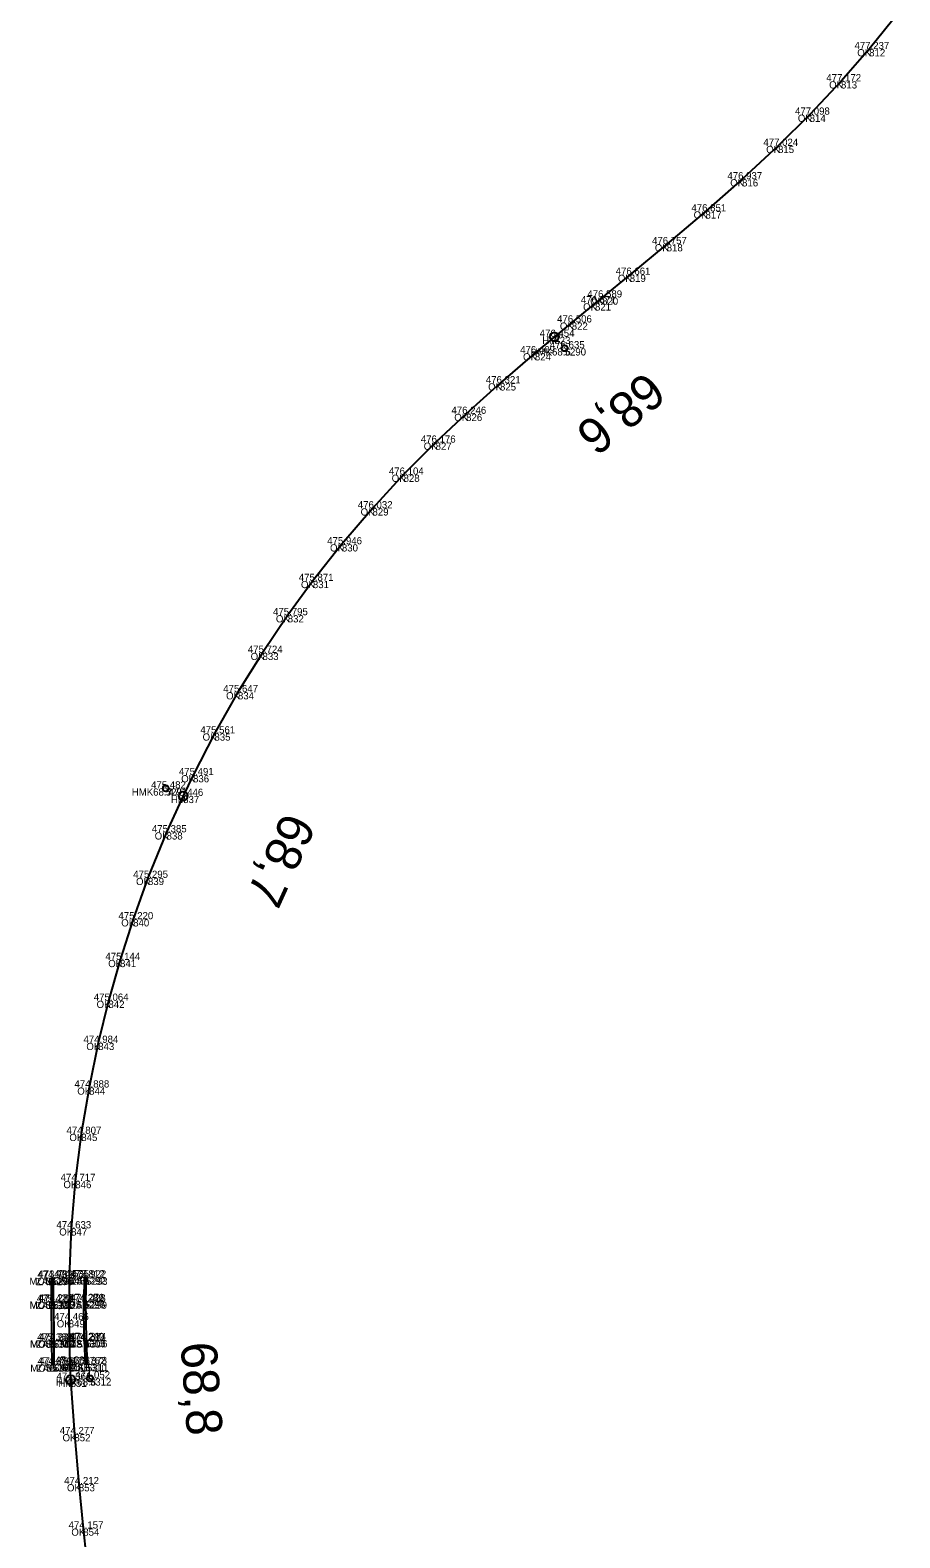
# Model space of a CAD drawing. Extents: x -621782 to -610392, y -1141853 to -1122321.
# Drawn here: x -621684.4 to -621539.3, y -1125595.1 to -1125343.5 of the extents above; entities that cross this region are included whole.
import ezdxf

# ---------------------------------------------------------------- set-up
doc = ezdxf.new("R2010")
doc.units = 0
for name, color, linetype in [('Vrstva 1', 7, 'Continuous'), ('Vrstva 17', 7, 'Continuous'), ('Vrstva 18', 7, 'Continuous'), ('Vrstva 60', 7, 'Continuous'), ('Vrstva 61', 7, 'Continuous'), ('Vrstva 62', 7, 'Continuous'), ('Vrstva 7', 7, 'Continuous')]:
    doc.layers.add(name, color=color, linetype=linetype)

msp = doc.modelspace()

# ---------------------------------------------------------------- linework, layer by layer
at = {"layer": 'Vrstva 1'}
msp.add_lwpolyline([(-621539.34, -1125340.3), (-621544.45, -1125346.63), (-621549.15, -1125352), (-621554.37, -1125357.57), (-621559.65, -1125362.78), (-621565.65, -1125368.35), (-621571.75, -1125373.71), (-621578.22, -1125379.19), (-621584.39, -1125384.29), (-621589, -1125388.09), (-621590.18, -1125389.06), (-621594.06, -1125392.26), (-621596.96, -1125394.65), (-621600.21, -1125397.39), (-621606.03, -1125402.41), (-621611.68, -1125407.5), (-621616.77, -1125412.31), (-621622.11, -1125417.66), (-621627.3, -1125423.28), (-621632.4, -1125429.28), (-621637.24, -1125435.4), (-621641.43, -1125441.12), (-621645.64, -1125447.4), (-621649.74, -1125453.97), (-621653.66, -1125460.85), (-621657.23, -1125467.81), (-621658.88, -1125471.28), (-621661.64, -1125477.36), (-621664.75, -1125484.96), (-621667.22, -1125491.87), (-621669.4, -1125498.66), (-621671.34, -1125505.47), (-621673.05, -1125512.5), (-621674.56, -1125519.95), (-621675.87, -1125527.69), (-621676.87, -1125535.56), (-621677.57, -1125543.46), (-621677.92, -1125551.62), (-621677.97, -1125558.78), (-621677.77, -1125566.05), (-621677.65, -1125568.73), (-621677.02, -1125577.81), (-621676.28, -1125586.16), (-621675.54, -1125593.57), (-621675.23, -1125596.68)], dxfattribs=at)
at = {"layer": 'Vrstva 17'}
for points in [[(-621680.71, -1125566.19), (-621680.78, -1125562.18), (-621680.84, -1125555.75), (-621680.85, -1125551.75)], [(-621675.06, -1125551.69), (-621675.15, -1125555.68), (-621675.07, -1125562.11), (-621674.92, -1125566.12)]]:
    msp.add_lwpolyline(points, dxfattribs=at)
at = {"layer": 'Vrstva 18'}
for points in [[(-621680.58, -1125551.69), (-621680.54, -1125555.65), (-621680.51, -1125555.71), (-621680.44, -1125562.17), (-621680.48, -1125562.2), (-621680.43, -1125566.19)], [(-621675.18, -1125566.13), (-621675.35, -1125562.18), (-621675.4, -1125562.1), (-621675.46, -1125555.65), (-621675.42, -1125555.59), (-621675.34, -1125551.63)]]:
    msp.add_lwpolyline(points, dxfattribs=at)
at = {"layer": 'Vrstva 60'}
for p, q in [((-621544.45, -1125346.63), (-621544.45, -1125346.63)), ((-621549.15, -1125352), (-621549.15, -1125352)), ((-621554.37, -1125357.57), (-621554.37, -1125357.57)), ((-621559.65, -1125362.78), (-621559.65, -1125362.78)), ((-621565.65, -1125368.35), (-621565.65, -1125368.35)), ((-621571.75, -1125373.71), (-621571.75, -1125373.71)), ((-621578.22, -1125379.19), (-621578.22, -1125379.19)), ((-621584.39, -1125384.29), (-621584.39, -1125384.29)), ((-621589, -1125388.09), (-621589, -1125388.09)), ((-621590.18, -1125389.06), (-621590.18, -1125389.06)), ((-621594.06, -1125392.26), (-621594.06, -1125392.26)), ((-621596.96, -1125394.65), (-621596.96, -1125394.65)), ((-621600.21, -1125397.39), (-621600.21, -1125397.39)), ((-621595.25, -1125396.57), (-621595.25, -1125396.57)), ((-621606.03, -1125402.41), (-621606.03, -1125402.41)), ((-621611.68, -1125407.5), (-621611.68, -1125407.5)), ((-621616.77, -1125412.31), (-621616.77, -1125412.31)), ((-621622.11, -1125417.66), (-621622.11, -1125417.66)), ((-621627.3, -1125423.28), (-621627.3, -1125423.28)), ((-621632.4, -1125429.28), (-621632.4, -1125429.28)), ((-621637.24, -1125435.4), (-621637.24, -1125435.4)), ((-621641.43, -1125441.12), (-621641.43, -1125441.12)), ((-621645.64, -1125447.4), (-621645.64, -1125447.4)), ((-621649.74, -1125453.97), (-621649.74, -1125453.97)), ((-621653.66, -1125460.85), (-621653.66, -1125460.85)), ((-621657.23, -1125467.81), (-621657.23, -1125467.81)), ((-621661.78, -1125470.03), (-621661.78, -1125470.03)), ((-621658.88, -1125471.28), (-621658.88, -1125471.28)), ((-621661.64, -1125477.36), (-621661.64, -1125477.36)), ((-621664.75, -1125484.96), (-621664.75, -1125484.96)), ((-621667.22, -1125491.87), (-621667.22, -1125491.87)), ((-621669.4, -1125498.66), (-621669.4, -1125498.66)), ((-621671.34, -1125505.47), (-621671.34, -1125505.47)), ((-621673.05, -1125512.5), (-621673.05, -1125512.5)), ((-621674.56, -1125519.95), (-621674.56, -1125519.95)), ((-621675.87, -1125527.69), (-621675.87, -1125527.69)), ((-621676.87, -1125535.56), (-621676.87, -1125535.56)), ((-621677.57, -1125543.46), (-621677.57, -1125543.46)), ((-621680.85, -1125551.75), (-621680.85, -1125551.75)), ((-621680.58, -1125551.69), (-621680.58, -1125551.69)), ((-621677.92, -1125551.62), (-621677.92, -1125551.62)), ((-621675.34, -1125551.63), (-621675.34, -1125551.63)), ((-621675.06, -1125551.69), (-621675.06, -1125551.69)), ((-621680.84, -1125555.75), (-621680.84, -1125555.75)), ((-621680.54, -1125555.65), (-621680.54, -1125555.65)), ((-621680.51, -1125555.71), (-621680.51, -1125555.71)), ((-621675.46, -1125555.65), (-621675.46, -1125555.65)), ((-621675.42, -1125555.59), (-621675.42, -1125555.59)), ((-621675.15, -1125555.68), (-621675.15, -1125555.68)), ((-621677.97, -1125558.78), (-621677.97, -1125558.78)), ((-621680.78, -1125562.18), (-621680.78, -1125562.18)), ((-621680.48, -1125562.2), (-621680.48, -1125562.2)), ((-621680.44, -1125562.17), (-621680.44, -1125562.17)), ((-621675.4, -1125562.1), (-621675.4, -1125562.1)), ((-621675.35, -1125562.18), (-621675.35, -1125562.18)), ((-621675.07, -1125562.11), (-621675.07, -1125562.11)), ((-621680.71, -1125566.19), (-621680.71, -1125566.19)), ((-621680.43, -1125566.19), (-621680.43, -1125566.19)), ((-621677.77, -1125566.05), (-621677.77, -1125566.05)), ((-621675.18, -1125566.13), (-621675.18, -1125566.13)), ((-621674.92, -1125566.12), (-621674.92, -1125566.12)), ((-621677.65, -1125568.73), (-621677.65, -1125568.73)), ((-621674.43, -1125568.51), (-621674.43, -1125568.51)), ((-621677.02, -1125577.81), (-621677.02, -1125577.81)), ((-621676.28, -1125586.16), (-621676.28, -1125586.16)), ((-621675.54, -1125593.57), (-621675.54, -1125593.57))]:
    msp.add_line(p, q, dxfattribs=at)
at = {"layer": 'Vrstva 7'}
for p, q in [((-621595.21, -1125396.54), (-621595.29, -1125396.6)), ((-621661.76, -1125469.98), (-621661.8, -1125470.07)), ((-621674.44, -1125568.46), (-621674.43, -1125568.56))]:
    msp.add_line(p, q, dxfattribs=at)
for centre, radius in [((-621596.96, -1125394.65), 0.75), ((-621595.25, -1125396.57), 0.5), ((-621661.78, -1125470.03), 0.5), ((-621658.88, -1125471.28), 0.75), ((-621677.65, -1125568.73), 0.75), ((-621674.43, -1125568.51), 0.5)]:
    msp.add_circle(centre, radius, dxfattribs=at)

# ---------------------------------------------------------------- texts
at = {"layer": 'Vrstva 60'}
for s, p in [('812', (-621544.45, -1125347.83)), ('813', (-621549.15, -1125353.2)), ('814', (-621554.37, -1125358.77)), ('815', (-621559.65, -1125363.98)), ('816', (-621565.65, -1125369.55)), ('817', (-621571.75, -1125374.91)), ('818', (-621578.22, -1125380.39)), ('819', (-621584.39, -1125385.49)), ('820', (-621589, -1125389.29)), ('821', (-621590.18, -1125390.26)), ('822', (-621594.06, -1125393.46)), ('823', (-621596.96, -1125395.85)), ('824', (-621600.21, -1125398.59)), ('5290', (-621595.25, -1125397.77)), ('825', (-621606.03, -1125403.61)), ('826', (-621611.68, -1125408.7)), ('827', (-621616.77, -1125413.51)), ('828', (-621622.11, -1125418.86)), ('829', (-621627.3, -1125424.48)), ('830', (-621632.4, -1125430.48)), ('831', (-621637.24, -1125436.6)), ('832', (-621641.43, -1125442.32)), ('833', (-621645.64, -1125448.6)), ('834', (-621649.74, -1125455.17)), ('835', (-621653.66, -1125462.05)), ('836', (-621657.23, -1125469.01)), ('5291', (-621661.78, -1125471.23)), ('837', (-621658.88, -1125472.48)), ('838', (-621661.64, -1125478.56)), ('839', (-621664.75, -1125486.16)), ('840', (-621667.22, -1125493.07)), ('841', (-621669.4, -1125499.86)), ('842', (-621671.34, -1125506.67)), ('843', (-621673.05, -1125513.7)), ('844', (-621674.56, -1125521.15)), ('845', (-621675.87, -1125528.89)), ('846', (-621676.87, -1125536.76)), ('847', (-621677.57, -1125544.66)), ('5295', (-621680.85, -1125552.95)), ('5294', (-621680.58, -1125552.89)), ('848', (-621677.92, -1125552.82)), ('5292', (-621675.34, -1125552.83)), ('5293', (-621675.06, -1125552.89)), ('5301', (-621680.84, -1125556.95)), ('5298', (-621680.54, -1125556.85)), ('5300', (-621680.51, -1125556.91)), ('5297', (-621675.46, -1125556.85)), ('5296', (-621675.42, -1125556.79)), ('5299', (-621675.15, -1125556.88)), ('849', (-621677.97, -1125559.99)), ('5303', (-621680.78, -1125563.38)), ('5304', (-621680.48, -1125563.4)), ('5302', (-621680.44, -1125563.37)), ('5305', (-621675.4, -1125563.3)), ('5307', (-621675.35, -1125563.38)), ('5306', (-621675.07, -1125563.31)), ('5308', (-621680.71, -1125567.39)), ('5309', (-621680.43, -1125567.39)), ('850', (-621677.77, -1125567.25)), ('5310', (-621675.18, -1125567.33)), ('5311', (-621674.92, -1125567.32)), ('851', (-621677.65, -1125569.93)), ('5312', (-621674.43, -1125569.71)), ('852', (-621677.02, -1125579.01)), ('853', (-621676.28, -1125587.36)), ('854', (-621675.54, -1125594.77))]:
    msp.add_text(s, height=1.2, dxfattribs=at).set_placement(p)
at = {"layer": 'Vrstva 61'}
for s, p in [('477.237', (-621546.9, -1125346.63)), ('477.172', (-621551.6, -1125352)), ('477.098', (-621556.82, -1125357.57)), ('477.024', (-621562.1, -1125362.78)), ('476.937', (-621568.1, -1125368.35)), ('476.851', (-621574.1, -1125373.71)), ('476.757', (-621580.67, -1125379.19)), ('476.661', (-621586.74, -1125384.29)), ('476.571', (-621592.54, -1125389.06)), ('476.589', (-621591.46, -1125388.09)), ('476.506', (-621596.51, -1125392.26)), ('476.454', (-621599.41, -1125394.65)), ('476.409', (-621602.66, -1125397.39)), ('476.635', (-621597.71, -1125396.57)), ('476.321', (-621608.39, -1125402.41)), ('476.246', (-621614.13, -1125407.5)), ('476.176', (-621619.23, -1125412.31)), ('476.104', (-621624.56, -1125417.66)), ('476.032', (-621629.75, -1125423.28)), ('475.946', (-621634.85, -1125429.28)), ('475.871', (-621639.6, -1125435.4)), ('475.795', (-621643.89, -1125441.12)), ('475.724', (-621648.09, -1125447.4)), ('475.647', (-621652.19, -1125453.97)), ('475.561', (-621656.01, -1125460.85)), ('475.491', (-621659.59, -1125467.81)), ('475.482', (-621664.23, -1125470.03)), ('475.446', (-621661.33, -1125471.28)), ('475.385', (-621664.1, -1125477.36)), ('475.295', (-621667.21, -1125484.96)), ('475.220', (-621669.67, -1125491.87)), ('475.144', (-621671.85, -1125498.66)), ('475.064', (-621673.79, -1125505.47)), ('474.984', (-621675.5, -1125512.5)), ('474.888', (-621677.01, -1125519.95)), ('474.807', (-621678.33, -1125527.69)), ('474.717', (-621679.32, -1125535.56)), ('474.633', (-621680.02, -1125543.46)), ('474.931', (-621683.21, -1125551.75)), ('473.789', (-621683.04, -1125551.69)), ('474.535', (-621680.38, -1125551.62)), ('473.812', (-621677.79, -1125551.63)), ('474.922', (-621677.51, -1125551.69)), ('475.420', (-621683.29, -1125555.75)), ('474.270', (-621682.99, -1125555.65)), ('474.287', (-621682.96, -1125555.71)), ('474.282', (-621677.91, -1125555.65)), ('474.276', (-621677.87, -1125555.59)), ('475.428', (-621677.6, -1125555.68)), ('474.466', (-621680.42, -1125558.78)), ('475.368', (-621683.23, -1125562.18)), ('474.235', (-621682.94, -1125562.2)), ('474.245', (-621682.9, -1125562.17)), ('474.240', (-621677.85, -1125562.1)), ('474.230', (-621677.8, -1125562.18)), ('475.374', (-621677.52, -1125562.11)), ('474.880', (-621683.16, -1125566.19)), ('473.766', (-621682.88, -1125566.19)), ('474.388', (-621680.23, -1125566.05)), ('473.762', (-621677.63, -1125566.13)), ('474.878', (-621677.38, -1125566.12)), ('474.361', (-621680.01, -1125568.73)), ('474.052', (-621676.88, -1125568.51)), ('474.277', (-621679.47, -1125577.81)), ('474.212', (-621678.73, -1125586.16)), ('474.157', (-621677.99, -1125593.57))]:
    msp.add_text(s, height=1.2, dxfattribs=at).set_placement(p)
at = {"layer": 'Vrstva 62'}
for s, p in [('OK', (-621546.44, -1125347.83)), ('OK', (-621551.13, -1125353.2)), ('OK', (-621556.35, -1125358.77)), ('OK', (-621561.63, -1125363.98)), ('OK', (-621567.63, -1125369.55)), ('OK', (-621573.73, -1125374.91)), ('OK', (-621580.2, -1125380.39)), ('OK', (-621586.37, -1125385.49)), ('OK', (-621590.99, -1125389.29)), ('OK', (-621592.17, -1125390.26)), ('OK', (-621596.04, -1125393.46)), ('HM', (-621598.99, -1125395.85)), ('OK', (-621602.19, -1125398.59)), ('HMK68.6', (-621600.92, -1125397.77)), ('OK', (-621608.01, -1125403.61)), ('OK', (-621613.66, -1125408.7)), ('OK', (-621618.76, -1125413.51)), ('OK', (-621624.1, -1125418.86)), ('OK', (-621629.28, -1125424.48)), ('OK', (-621634.38, -1125430.48)), ('OK', (-621639.23, -1125436.6)), ('OK', (-621643.41, -1125442.32)), ('OK', (-621647.62, -1125448.6)), ('OK', (-621651.72, -1125455.17)), ('OK', (-621655.64, -1125462.05)), ('OK', (-621659.21, -1125469.01)), ('HMK68.7', (-621667.45, -1125471.23)), ('HM', (-621660.92, -1125472.48)), ('OK', (-621663.63, -1125478.56)), ('OK', (-621666.74, -1125486.16)), ('OK', (-621669.21, -1125493.07)), ('OK', (-621671.38, -1125499.86)), ('OK', (-621673.32, -1125506.67)), ('OK', (-621675.03, -1125513.7)), ('OK', (-621676.54, -1125521.15)), ('OK', (-621677.86, -1125528.89)), ('OK', (-621678.85, -1125536.76)), ('OK', (-621679.55, -1125544.66)), ('MOST', (-621684.53, -1125552.89)), ('ZAB', (-621683.45, -1125552.95)), ('MOST', (-621681.87, -1125552.82)), ('MOST', (-621679.29, -1125552.83)), ('ZAB', (-621677.66, -1125552.89)), ('MOST', (-621684.49, -1125556.85)), ('MOST', (-621684.46, -1125556.91)), ('ZAB', (-621683.44, -1125556.95)), ('MOST', (-621679.41, -1125556.85)), ('MOST', (-621679.37, -1125556.79)), ('ZAB', (-621677.75, -1125556.88)), ('OK', (-621679.96, -1125559.99)), ('MOST', (-621684.43, -1125563.4)), ('MOST', (-621684.39, -1125563.37)), ('ZAB', (-621683.38, -1125563.38)), ('MOST', (-621679.34, -1125563.3)), ('MOST', (-621679.29, -1125563.38)), ('ZAB', (-621677.67, -1125563.31)), ('MOST', (-621684.38, -1125567.39)), ('ZAB', (-621683.31, -1125567.39)), ('MOST', (-621681.72, -1125567.25)), ('MOST', (-621679.13, -1125567.33)), ('ZAB', (-621677.52, -1125567.32)), ('HMK68.8', (-621680.1, -1125569.71)), ('HM', (-621679.68, -1125569.93)), ('OK', (-621679, -1125579.01)), ('OK', (-621678.26, -1125587.36)), ('OK', (-621677.53, -1125594.77))]:
    msp.add_text(s, height=1.2, dxfattribs=at).set_placement(p)
at = {"layer": 'Vrstva 7'}
for s, rotation, p in [('68,6', 219.5168, (-621581.7, -1125400.19)), ('68,7', 245.5837, (-621642.06, -1125473.71)), ('68,8', 273.9878, (-621659.31, -1125562.63))]:
    msp.add_text(s, height=6, rotation=rotation, dxfattribs=at).set_placement(p)

doc.saveas('drawing.dxf')
